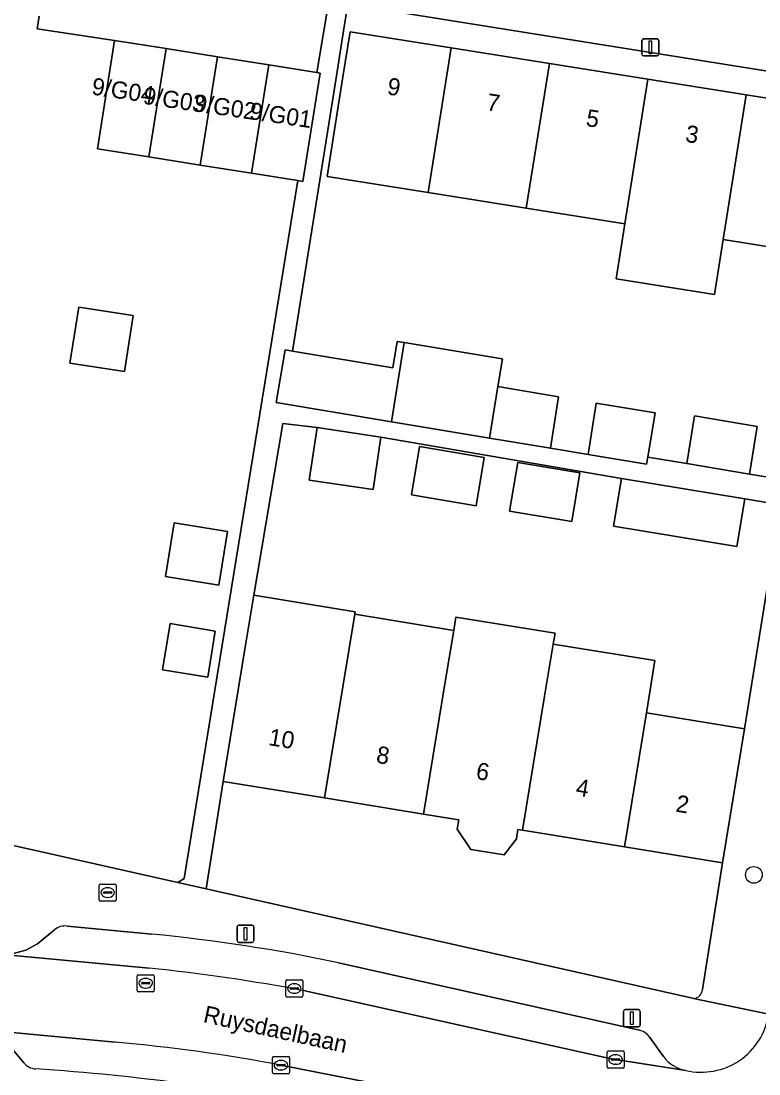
# Model space of a CAD drawing. Extents: x 163008 to 163854, y 382777 to 383982.
# Drawn here: x 163214.9 to 163258.1, y 383050.1 to 383111.7 of the extents above; entities that cross this region are included whole.
import ezdxf

# ---------------------------------------------------------------- set-up
doc = ezdxf.new("R2010")
doc.units = 0
for name, color, linetype in [('IMGEO_Boom', 7, 'Continuous'), ('IMGEO_Brandkraan', 7, 'Continuous'), ('IMGEO_Erf', 7, 'Continuous'), ('IMGEO_Kolk', 7, 'Continuous'), ('IMGEO_Lichtmast', 7, 'Continuous'), ('IMGEO_Muur', 7, 'Continuous'), ('IMGEO_Openbare_ruimte_label', 7, 'Continuous'), ('IMGEO_Pand', 7, 'Continuous'), ('IMGEO_Pand_nummerreeks', 7, 'Continuous'), ('IMGEO_Parkeervlak_open', 7, 'Continuous'), ('IMGEO_Rijbaan_lokaal_open', 7, 'Continuous'), ('IMGEO_Rioolput', 7, 'Continuous'), ('IMGEO_Voetpad_open', 7, 'Continuous')]:
    doc.layers.add(name, color=color, linetype=linetype)

msp = doc.modelspace()

# ---------------------------------------------------------------- linework, layer by layer
at = {"layer": 'IMGEO_Boom'}
msp.add_circle((163257.821, 383061.735), 0.489, dxfattribs=at)
at = {"layer": 'IMGEO_Brandkraan'}
for p, q in [((163219.508, 383060.272), (163219.508, 383061.124)), ((163219.583, 383061.198), (163220.435, 383061.198)), ((163219.996, 383060.978), (163220.021, 383060.978)), ((163220.509, 383061.124), (163220.509, 383060.272)), ((163219.767, 383060.692), (163219.767, 383060.704)), ((163220.205, 383060.655), (163219.807, 383060.655)), ((163219.81, 383060.741), (163220.208, 383060.741)), ((163220.019, 383060.418), (163219.994, 383060.418)), ((163220.251, 383060.704), (163220.251, 383060.692)), ((163220.435, 383060.198), (163219.583, 383060.198))]:
    msp.add_line(p, q, dxfattribs=at)
for points in [[(163219.508, 383060.272), (163219.508, 383061.124)], [(163219.583, 383061.198), (163220.435, 383061.198)], [(163220.509, 383061.124), (163220.509, 383060.272)], [(163220.435, 383060.198), (163219.583, 383060.198)]]:
    msp.add_lwpolyline(points, dxfattribs=at)
for centre, radius, start, end in [((163219.585, 383061.122), 0.0765, 91.55205, 178.44795), ((163219.585, 383061.122), 0.0765, 91.55205, 178.44795), ((163220.433, 383061.122), 0.0765, 1.55205, 88.44795), ((163220.433, 383061.122), 0.0765, 1.55205, 88.44795), ((163219.807, 383060.701), 0.0403, 85.87752, 175.75265), ((163219.804, 383060.691), 0.0366, 178.93798, 274.71019), ((163220.208, 383060.698), 0.043, 264.86636, 352.45326), ((163220.212, 383060.703), 0.0386, 1.73085, 96.63898), ((163219.585, 383060.274), 0.0765, 181.55205, 268.44795), ((163219.585, 383060.274), 0.0765, 181.55205, 268.44795), ((163220.433, 383060.274), 0.0765, 271.55205, 358.44795), ((163220.433, 383060.274), 0.0765, 271.55205, 358.44795)]:
    msp.add_arc(centre, radius, start, end, dxfattribs=at)
for centre, major_axis, ratio, start_param, end_param in [((163219.995, 383060.698), (-0.387, 0.002), 0.722429, 4.712389, 7.853982), ((163220.02, 383060.698), (-0.39, 0.002), 0.717154, 1.570796, 4.712389)]:
    msp.add_ellipse(centre, major_axis=major_axis, ratio=ratio, start_param=start_param, end_param=end_param, dxfattribs=at)
at = {"layer": 'IMGEO_Erf'}
for points in [[(163234.063, 383112.721), (163233.814, 383111.161), (163233.393, 383108.525), (163230.816, 383092.401), (163236.688, 383091.425), (163236.945, 383092.971), (163237.358, 383092.903), (163243.087, 383091.95), (163243.11, 383091.946), (163242.84, 383090.322), (163246.394, 383089.731), (163245.915, 383086.716), (163248.119, 383086.349), (163248.599, 383089.364), (163252.041, 383088.791), (163251.609, 383086.192), (163253.889, 383085.813), (163254.351, 383088.605), (163258.022, 383087.998), (163257.56, 383085.206), (163259.619, 383084.866)], [(163263.52, 383108.014), (163234.432, 383112.662)], [(163220.415, 383110.598), (163215.882, 383111.28), (163216.001, 383112.013)], [(163261.735, 383098.027), (163256.025, 383098.935), (163255.513, 383095.723), (163249.757, 383096.639), (163250.269, 383099.851), (163244.502, 383100.77), (163238.756, 383101.684), (163232.849, 383102.624), (163233.778, 383108.461), (163234.198, 383111.1), (163240.105, 383110.16), (163245.862, 383109.244), (163251.619, 383108.328), (163257.375, 383107.412), (163263.279, 383106.473)], [(163196.948, 383067.404), (163224.107, 383061.294), (163224.491, 383061.52), (163231.133, 383102.385), (163228.425, 383102.816), (163225.418, 383103.294), (163222.412, 383103.772), (163219.405, 383104.251), (163220.415, 383110.598)], [(163241.255, 383063.222), (163240.467, 383064.415), (163240.556, 383064.957), (163238.489, 383065.295), (163232.704, 383066.241), (163226.772, 383067.211), (163225.781, 383060.917), (163254.223, 383054.518), (163254.281, 383054.505)], [(163254.811, 383055.03), (163255.991, 383062.434), (163250.247, 383063.373), (163244.274, 383064.35), (163244.01, 383064.393), (163243.921, 383063.85), (163243.209, 383062.903), (163241.255, 383063.222)]]:
    msp.add_lwpolyline(points, dxfattribs=at)
for points in [[(163217.799, 383091.698), (163218.312, 383094.985), (163221.497, 383094.489), (163220.984, 383091.201)], [(163259.384, 383083.403), (163257.288, 383083.75), (163256.826, 383080.958), (163249.612, 383082.152), (163250.074, 383084.944), (163235.991, 383087.372), (163235.535, 383084.293), (163231.806, 383084.846), (163232.262, 383087.924), (163230.258, 383088.167), (163228.556, 383078.117), (163234.494, 383077.146), (163234.469, 383076.996), (163240.254, 383076.051), (163240.382, 383076.832), (163246.189, 383075.883), (163246.082, 383075.252), (163252.03, 383074.28), (163251.531, 383071.228), (163257.275, 383070.289)], [(163237.783, 383083.98), (163238.254, 383086.811), (163242.048, 383086.18), (163241.578, 383083.349)], [(163243.526, 383083.025), (163244, 383085.871), (163247.632, 383085.267), (163247.159, 383082.421)], [(163223.388, 383079.201), (163223.904, 383082.355), (163227.022, 383081.845), (163226.506, 383078.691)], [(163223.216, 383073.743), (163223.658, 383076.445), (163226.307, 383076.012), (163225.865, 383073.31)]]:
    msp.add_lwpolyline(points, close=True, dxfattribs=at)
msp.add_arc((163254.265, 383055.051), 0.546, 271.66367, 357.79325, dxfattribs=at)
at = {"layer": 'IMGEO_Kolk'}
for p, q in [((163230.431, 383054.656), (163230.431, 383055.508)), ((163230.506, 383055.582), (163231.358, 383055.582)), ((163231.432, 383055.508), (163231.432, 383054.656)), ((163230.69, 383055.076), (163230.69, 383055.088)), ((163231.128, 383055.039), (163230.73, 383055.039)), ((163230.733, 383055.125), (163231.131, 383055.125)), ((163230.919, 383055.362), (163230.944, 383055.362)), ((163231.174, 383055.088), (163231.174, 383055.076)), ((163231.358, 383054.582), (163230.506, 383054.582)), ((163230.942, 383054.802), (163230.917, 383054.802)), ((163249.227, 383050.496), (163249.227, 383051.348)), ((163249.302, 383051.422), (163250.154, 383051.422)), ((163249.715, 383051.202), (163249.74, 383051.202)), ((163250.228, 383051.348), (163250.228, 383050.496)), ((163229.646, 383050.167), (163229.646, 383051.019)), ((163229.721, 383051.093), (163230.573, 383051.093)), ((163229.905, 383050.587), (163229.905, 383050.599)), ((163230.343, 383050.55), (163229.945, 383050.55)), ((163229.948, 383050.636), (163230.346, 383050.636)), ((163230.134, 383050.873), (163230.159, 383050.873)), ((163230.389, 383050.599), (163230.389, 383050.587)), ((163230.647, 383051.019), (163230.647, 383050.167)), ((163249.486, 383050.916), (163249.486, 383050.928)), ((163249.924, 383050.879), (163249.526, 383050.879)), ((163249.529, 383050.965), (163249.927, 383050.965)), ((163249.738, 383050.642), (163249.713, 383050.642)), ((163249.97, 383050.928), (163249.97, 383050.916)), ((163230.573, 383050.093), (163229.721, 383050.093)), ((163230.157, 383050.313), (163230.132, 383050.313)), ((163250.154, 383050.422), (163249.302, 383050.422))]:
    msp.add_line(p, q, dxfattribs=at)
for points in [[(163230.431, 383054.656), (163230.431, 383055.508)], [(163230.506, 383055.582), (163231.358, 383055.582)], [(163231.432, 383055.508), (163231.432, 383054.656)], [(163231.358, 383054.582), (163230.506, 383054.582)], [(163249.227, 383050.496), (163249.227, 383051.348)], [(163249.302, 383051.422), (163250.154, 383051.422)], [(163250.228, 383051.348), (163250.228, 383050.496)], [(163229.646, 383050.167), (163229.646, 383051.019)], [(163229.721, 383051.093), (163230.573, 383051.093)], [(163230.647, 383051.019), (163230.647, 383050.167)], [(163230.573, 383050.093), (163229.721, 383050.093)], [(163250.154, 383050.422), (163249.302, 383050.422)]]:
    msp.add_lwpolyline(points, dxfattribs=at)
for centre, radius, start, end in [((163230.508, 383055.506), 0.0765, 91.55205, 178.44795), ((163230.508, 383055.506), 0.0765, 91.55205, 178.44795), ((163231.356, 383055.506), 0.0765, 1.55205, 88.44795), ((163231.356, 383055.506), 0.0765, 1.55205, 88.44795), ((163230.73, 383055.085), 0.0403, 85.87752, 175.75265), ((163230.727, 383055.075), 0.0366, 178.93798, 274.71019), ((163231.131, 383055.082), 0.043, 264.86636, 352.45326), ((163231.135, 383055.087), 0.0386, 1.73085, 96.63898), ((163230.508, 383054.658), 0.0765, 181.55205, 268.44795), ((163230.508, 383054.658), 0.0765, 181.55205, 268.44795), ((163231.356, 383054.658), 0.0765, 271.55205, 358.44795), ((163231.356, 383054.658), 0.0765, 271.55205, 358.44795), ((163249.304, 383051.346), 0.0765, 91.55205, 178.44795), ((163249.304, 383051.346), 0.0765, 91.55205, 178.44795), ((163250.152, 383051.346), 0.0765, 1.55205, 88.44795), ((163250.152, 383051.346), 0.0765, 1.55205, 88.44795), ((163229.723, 383051.017), 0.0765, 91.55205, 178.44795), ((163229.723, 383051.017), 0.0765, 91.55205, 178.44795), ((163229.945, 383050.596), 0.0403, 85.87752, 175.75265), ((163229.942, 383050.586), 0.0366, 178.93798, 274.71019), ((163230.346, 383050.593), 0.043, 264.86636, 352.45326), ((163230.35, 383050.598), 0.0386, 1.73085, 96.63898), ((163230.571, 383051.017), 0.0765, 1.55205, 88.44795), ((163230.571, 383051.017), 0.0765, 1.55205, 88.44795), ((163249.304, 383050.498), 0.0765, 181.55205, 268.44795), ((163249.304, 383050.498), 0.0765, 181.55205, 268.44795), ((163249.526, 383050.925), 0.0403, 85.87752, 175.75265), ((163249.523, 383050.915), 0.0366, 178.93798, 274.71019), ((163249.927, 383050.922), 0.043, 264.86636, 352.45326), ((163249.931, 383050.927), 0.0386, 1.73085, 96.63898), ((163250.152, 383050.498), 0.0765, 271.55205, 358.44795), ((163250.152, 383050.498), 0.0765, 271.55205, 358.44795), ((163229.723, 383050.169), 0.0765, 181.55205, 268.44795), ((163229.723, 383050.169), 0.0765, 181.55205, 268.44795), ((163230.571, 383050.169), 0.0765, 271.55205, 358.44795), ((163230.571, 383050.169), 0.0765, 271.55205, 358.44795)]:
    msp.add_arc(centre, radius, start, end, dxfattribs=at)
for centre, major_axis, ratio, start_param, end_param in [((163230.918, 383055.082), (-0.387, 0.002), 0.722429, 4.712389, 7.853982), ((163230.943, 383055.082), (-0.39, 0.002), 0.717154, 1.570796, 4.712389), ((163249.714, 383050.922), (-0.387, 0.002), 0.722429, 4.712389, 7.853982), ((163249.739, 383050.922), (-0.39, 0.002), 0.717154, 1.570796, 4.712389), ((163230.133, 383050.593), (-0.387, 0.002), 0.722429, 4.712389, 7.853982), ((163230.158, 383050.593), (-0.39, 0.002), 0.717154, 1.570796, 4.712389)]:
    msp.add_ellipse(centre, major_axis=major_axis, ratio=ratio, start_param=start_param, end_param=end_param, dxfattribs=at)
at = {"layer": 'IMGEO_Lichtmast'}
for p, q in [((163251.268, 383109.787), (163251.268, 383110.587)), ((163251.268, 383110.587), (163251.268, 383109.787)), ((163251.368, 383110.687), (163252.158, 383110.687)), ((163252.158, 383110.687), (163251.368, 383110.687)), ((163252.258, 383110.587), (163252.258, 383109.787)), ((163252.258, 383109.787), (163252.258, 383110.587)), ((163252.158, 383109.687), (163251.368, 383109.687)), ((163251.368, 383109.687), (163252.158, 383109.687)), ((163227.577, 383057.884), (163227.577, 383058.684)), ((163227.577, 383058.684), (163227.577, 383057.884)), ((163227.677, 383058.784), (163228.467, 383058.784)), ((163228.467, 383058.784), (163227.677, 383058.784)), ((163228.567, 383058.684), (163228.567, 383057.884)), ((163228.567, 383057.884), (163228.567, 383058.684)), ((163228.467, 383057.784), (163227.677, 383057.784)), ((163227.677, 383057.784), (163228.467, 383057.784)), ((163250.186, 383052.943), (163250.186, 383053.743)), ((163250.186, 383053.743), (163250.186, 383052.943)), ((163250.286, 383053.843), (163251.076, 383053.843)), ((163251.076, 383053.843), (163250.286, 383053.843)), ((163251.176, 383053.743), (163251.176, 383052.943)), ((163251.176, 383052.943), (163251.176, 383053.743)), ((163251.076, 383052.843), (163250.286, 383052.843)), ((163250.286, 383052.843), (163251.076, 383052.843))]:
    msp.add_line(p, q, dxfattribs=at)
for points in [[(163251.688, 383110.562), (163251.838, 383110.562), (163251.838, 383109.812), (163251.688, 383109.812), (163251.688, 383110.562)], [(163227.997, 383058.659), (163228.147, 383058.659), (163228.147, 383057.909), (163227.997, 383057.909), (163227.997, 383058.659)], [(163250.606, 383053.718), (163250.756, 383053.718), (163250.756, 383052.968), (163250.606, 383052.968), (163250.606, 383053.718)]]:
    msp.add_lwpolyline(points, dxfattribs=at)
for centre, start, end in [((163251.368, 383110.587), 90, 180), ((163251.368, 383110.587), 90, 180), ((163252.158, 383110.587), 0, 90), ((163252.158, 383110.587), 360, 90), ((163251.368, 383109.787), 180, 270), ((163251.368, 383109.787), 180, 270), ((163252.158, 383109.787), 270, 0), ((163252.158, 383109.787), 270, 0), ((163227.677, 383058.684), 90, 180), ((163227.677, 383058.684), 90, 180), ((163228.467, 383058.684), 0, 90), ((163228.467, 383058.684), 360, 90), ((163227.677, 383057.884), 180, 270), ((163227.677, 383057.884), 180, 270), ((163228.467, 383057.884), 270, 0), ((163228.467, 383057.884), 270, 0), ((163250.286, 383053.743), 90, 180), ((163250.286, 383053.743), 90, 180), ((163251.076, 383053.743), 0, 90), ((163251.076, 383053.743), 360, 90), ((163250.286, 383052.943), 180, 270), ((163250.286, 383052.943), 180, 270), ((163251.076, 383052.943), 270, 0), ((163251.076, 383052.943), 270, 0)]:
    msp.add_arc(centre, 0.1, start, end, dxfattribs=at)
at = {"layer": 'IMGEO_Muur'}
msp.add_lwpolyline([(163257.275, 383070.289), (163259.384, 383083.403)], dxfattribs=at)
at = {"layer": 'IMGEO_Pand'}
for points in [[(163240.105, 383110.16), (163234.198, 383111.1), (163233.778, 383108.461), (163232.849, 383102.624), (163238.756, 383101.684)], [(163223.422, 383110.12), (163220.415, 383110.598), (163219.405, 383104.251), (163222.412, 383103.772)], [(163225.418, 383103.294), (163226.429, 383109.641), (163223.422, 383110.12), (163222.412, 383103.772)], [(163240.105, 383110.16), (163238.756, 383101.684), (163244.502, 383100.77), (163245.862, 383109.244)], [(163229.435, 383109.163), (163226.429, 383109.641), (163225.418, 383103.294), (163228.425, 383102.816)], [(163232.442, 383108.684), (163232.25, 383108.715), (163229.435, 383109.163), (163228.425, 383102.816), (163231.133, 383102.385), (163231.432, 383102.337)], [(163251.619, 383108.328), (163245.862, 383109.244), (163244.502, 383100.77), (163250.269, 383099.851)], [(163257.375, 383107.412), (163251.619, 383108.328), (163250.269, 383099.851), (163249.757, 383096.639), (163255.513, 383095.723), (163256.025, 383098.935)], [(163256.025, 383098.935), (163261.735, 383098.027), (163261.93, 383097.996), (163263.279, 383106.473), (163257.375, 383107.412)], [(163217.799, 383091.698), (163220.984, 383091.201), (163221.497, 383094.489), (163218.312, 383094.985)], [(163237.358, 383092.903), (163236.945, 383092.971), (163236.688, 383091.425), (163230.816, 383092.401), (163230.386, 383092.473), (163229.873, 383089.384), (163236.62, 383088.262)], [(163242.342, 383087.31), (163242.84, 383090.322), (163243.11, 383091.946), (163243.087, 383091.95), (163237.358, 383092.903), (163236.62, 383088.262)], [(163246.394, 383089.731), (163242.84, 383090.322), (163242.342, 383087.31), (163245.915, 383086.716)], [(163252.041, 383088.791), (163248.599, 383089.364), (163248.119, 383086.349), (163251.541, 383085.78), (163251.609, 383086.192)], [(163257.56, 383085.206), (163258.022, 383087.998), (163254.351, 383088.605), (163253.889, 383085.813)], [(163232.262, 383087.924), (163231.806, 383084.846), (163235.535, 383084.293), (163235.991, 383087.372)], [(163237.783, 383083.98), (163241.578, 383083.349), (163242.048, 383086.18), (163238.254, 383086.811)], [(163243.526, 383083.025), (163247.159, 383082.421), (163247.632, 383085.267), (163244, 383085.871)], [(163256.826, 383080.958), (163257.288, 383083.75), (163250.074, 383084.944), (163249.612, 383082.152)], [(163223.388, 383079.201), (163226.506, 383078.691), (163227.022, 383081.845), (163223.904, 383082.355)], [(163234.469, 383076.996), (163234.494, 383077.146), (163228.556, 383078.117), (163228.057, 383075.066), (163226.772, 383067.211), (163232.704, 383066.241)], [(163223.216, 383073.743), (163225.865, 383073.31), (163226.307, 383076.012), (163223.658, 383076.445)], [(163239.778, 383073.15), (163240.254, 383076.051), (163234.469, 383076.996), (163232.704, 383066.241), (163238.489, 383065.295)], [(163245.563, 383072.204), (163246.082, 383075.252), (163246.189, 383075.883), (163240.382, 383076.832), (163240.254, 383076.051), (163239.778, 383073.15), (163238.489, 383065.295), (163240.556, 383064.957), (163240.467, 383064.415), (163241.255, 383063.222), (163243.209, 383062.903), (163243.921, 383063.85), (163244.01, 383064.393), (163244.274, 383064.35)], [(163244.274, 383064.35), (163250.247, 383063.373), (163251.531, 383071.228), (163252.03, 383074.28), (163246.082, 383075.252), (163245.563, 383072.204)], [(163250.247, 383063.373), (163255.991, 383062.434), (163257.275, 383070.289), (163251.531, 383071.228)]]:
    msp.add_lwpolyline(points, close=True, dxfattribs=at)
at = {"layer": 'IMGEO_Parkeervlak_open'}
for points in [[(163216.903, 383058.523), (163215.907, 383057.7), (163215.212, 383057.322), (163214.427, 383057.113), (163214.493, 383057.014), (163222.435, 383056.273)], [(163222.584, 383058.266), (163217.637, 383058.738)], [(163251.122, 383052.633), (163233.514, 383056.59)], [(163231.543, 383054.945), (163249.397, 383050.985), (163249.727, 383050.921), (163253.832, 383050.282)], [(163220.449, 383051.941), (163213.372, 383052.604), (163212.774, 383052.68), (163213.503, 383052.384), (163214.13, 383051.894), (163215.105, 383050.732)], [(163252.529, 383051.101), (163251.726, 383052.222)], [(163252.989, 383045.319), (163248.808, 383046.48), (163248.375, 383046.61), (163235.315, 383049.584), (163230.147, 383050.595)]]:
    msp.add_lwpolyline(points, dxfattribs=at)
for centre, radius, start, end in [((163217.524, 383057.764), 0.98, 83.36181, 129.29044), ((163212.795, 382957.949), 100.794, 78.13775, 84.42665), ((163210.919, 382945.392), 111.478, 79.33837, 84.07042), ((163250.974, 383051.766), 0.879, 31.21931, 80.31297), ((163211.356, 382950.817), 101.532, 79.33467, 84.86195), ((163215.869, 383051.349), 0.982, 218.92686, 264.8666), ((163254.222, 383052.349), 2.104, 216.39068, 259.30653), ((163208.147, 382929.517), 121.094, 77.85148, 86.38563)]:
    msp.add_arc(centre, radius, start, end, dxfattribs=at)
at = {"layer": 'IMGEO_Rijbaan_lokaal_open'}
for points in [[(163216.001, 383112.013), (163215.882, 383111.28), (163220.415, 383110.598), (163223.422, 383110.12), (163226.429, 383109.641), (163229.435, 383109.163), (163232.25, 383108.715), (163232.95, 383112.902), (163213.087, 383116.121)], [(163222.435, 383056.273), (163214.493, 383057.014), (163214.427, 383057.113), (163213.659, 383057.003)], [(163253.832, 383050.282), (163249.727, 383050.921), (163249.397, 383050.985), (163231.543, 383054.945)], [(163212.774, 383052.68), (163213.372, 383052.604), (163220.449, 383051.941)], [(163230.147, 383050.595), (163235.315, 383049.584), (163248.375, 383046.61), (163248.808, 383046.48), (163252.989, 383045.319)]]:
    msp.add_lwpolyline(points, dxfattribs=at)
for centre, radius, start, end in [((163210.919, 382945.392), 111.478, 79.33837, 84.07042), ((163254.731, 383054.183), 4.004, 257.02711, 351.27382), ((163211.356, 382950.817), 101.532, 79.33467, 84.86195)]:
    msp.add_arc(centre, radius, start, end, dxfattribs=at)
at = {"layer": 'IMGEO_Rioolput'}
for p, q in [((163221.732, 383054.964), (163221.732, 383055.816)), ((163221.807, 383055.89), (163222.659, 383055.89)), ((163222.034, 383055.433), (163222.432, 383055.433)), ((163222.22, 383055.67), (163222.245, 383055.67)), ((163222.733, 383055.816), (163222.733, 383054.964)), ((163222.659, 383054.89), (163221.807, 383054.89)), ((163221.991, 383055.384), (163221.991, 383055.396)), ((163222.429, 383055.347), (163222.031, 383055.347)), ((163222.243, 383055.11), (163222.218, 383055.11)), ((163222.475, 383055.396), (163222.475, 383055.384))]:
    msp.add_line(p, q, dxfattribs=at)
for points in [[(163221.732, 383054.964), (163221.732, 383055.816)], [(163221.807, 383055.89), (163222.659, 383055.89)], [(163222.733, 383055.816), (163222.733, 383054.964)], [(163222.659, 383054.89), (163221.807, 383054.89)]]:
    msp.add_lwpolyline(points, dxfattribs=at)
for centre, radius, start, end in [((163221.809, 383055.814), 0.0765, 91.55205, 178.44795), ((163221.809, 383055.814), 0.0765, 91.55205, 178.44795), ((163222.031, 383055.393), 0.0403, 85.87752, 175.75265), ((163222.436, 383055.395), 0.0386, 1.73085, 96.63898), ((163222.657, 383055.814), 0.0765, 1.55205, 88.44795), ((163222.657, 383055.814), 0.0765, 1.55205, 88.44795), ((163221.809, 383054.966), 0.0765, 181.55205, 268.44795), ((163221.809, 383054.966), 0.0765, 181.55205, 268.44795), ((163222.028, 383055.383), 0.0366, 178.93798, 274.71019), ((163222.432, 383055.39), 0.043, 264.86636, 352.45326), ((163222.657, 383054.966), 0.0765, 271.55205, 358.44795), ((163222.657, 383054.966), 0.0765, 271.55205, 358.44795)]:
    msp.add_arc(centre, radius, start, end, dxfattribs=at)
for centre, major_axis, ratio, start_param, end_param in [((163222.219, 383055.39), (-0.387, 0.002), 0.722429, 4.712389, 7.853982), ((163222.244, 383055.39), (-0.39, 0.002), 0.717154, 1.570796, 4.712389)]:
    msp.add_ellipse(centre, major_axis=major_axis, ratio=ratio, start_param=start_param, end_param=end_param, dxfattribs=at)
at = {"layer": 'IMGEO_Voetpad_open'}
for points in [[(163271.991, 383163.012), (163270.324, 383152.219), (163270.282, 383151.95), (163270.099, 383150.762), (163268.457, 383140.137), (163267.168, 383132.16), (163266.909, 383130.633), (163266.291, 383126.455), (163266.288, 383126.43), (163264.176, 383112.34), (163264.173, 383112.32), (163263.52, 383108.014), (163263.279, 383106.473), (163261.93, 383097.996), (163261.735, 383098.027), (163259.619, 383084.866), (163259.384, 383083.403), (163257.275, 383070.289), (163255.991, 383062.434), (163254.811, 383055.03)], [(163266.291, 383126.455), (163266.909, 383130.633), (163237.819, 383135.321), (163237.896, 383135.882), (163236.759, 383136.055), (163236.517, 383136.095), (163233.783, 383117.895), (163233.769, 383117.799), (163233.721, 383117.514), (163232.95, 383112.902), (163234.063, 383112.721), (163234.432, 383112.662), (163263.52, 383108.014), (163264.173, 383112.32)], [(163232.95, 383112.902), (163232.25, 383108.715), (163232.442, 383108.684), (163231.432, 383102.337), (163231.133, 383102.385), (163224.491, 383061.52), (163224.107, 383061.294), (163225.781, 383060.917), (163226.772, 383067.211), (163228.057, 383075.066), (163228.556, 383078.117), (163230.258, 383088.167), (163232.262, 383087.924), (163235.991, 383087.372), (163250.074, 383084.944), (163257.288, 383083.75), (163259.384, 383083.403)], [(163259.619, 383084.866), (163257.56, 383085.206), (163253.889, 383085.813), (163251.609, 383086.192), (163251.541, 383085.78), (163248.119, 383086.349), (163245.915, 383086.716), (163242.342, 383087.31), (163236.62, 383088.262), (163229.873, 383089.384), (163230.386, 383092.473), (163230.816, 383092.401), (163233.393, 383108.525), (163233.814, 383111.161), (163234.063, 383112.721)], [(163258.688, 383053.576), (163254.281, 383054.505), (163254.223, 383054.518), (163225.781, 383060.917), (163224.107, 383061.294), (163196.948, 383067.404)], [(163254.281, 383054.505), (163258.688, 383053.576), (163259.673, 383059.48), (163259.821, 383060.729)], [(163213.659, 383057.003), (163214.427, 383057.113), (163215.212, 383057.322), (163215.907, 383057.7), (163216.903, 383058.523)], [(163217.637, 383058.738), (163222.584, 383058.266)], [(163233.514, 383056.59), (163251.122, 383052.633)], [(163215.105, 383050.732), (163214.13, 383051.894), (163213.503, 383052.384), (163212.774, 383052.68)], [(163251.726, 383052.222), (163252.529, 383051.101)]]:
    msp.add_lwpolyline(points, dxfattribs=at)
for centre, radius, start, end in [((163217.524, 383057.764), 0.98, 83.36181, 129.29044), ((163212.795, 382957.949), 100.794, 78.13775, 84.42665), ((163254.265, 383055.051), 0.546, 271.66367, 357.79325), ((163254.731, 383054.183), 4.004, 257.02711, 351.27382), ((163250.974, 383051.766), 0.879, 31.21931, 80.31297), ((163215.869, 383051.349), 0.982, 218.92686, 264.8666), ((163254.222, 383052.349), 2.104, 216.39068, 259.30653), ((163208.147, 382929.517), 121.094, 77.85148, 86.38563)]:
    msp.add_arc(centre, radius, start, end, dxfattribs=at)

# ---------------------------------------------------------------- texts
at = {"layer": 'IMGEO_Openbare_ruimte_label'}
msp.add_text('Ruysdaelbaan', height=1, rotation=347.70114, dxfattribs=at).set_placement((163225.55, 383053.12))
at = {"layer": 'IMGEO_Pand_nummerreeks'}
for s, rotation, p in [('9/G04', 351.57402, (163219.03, 383107.434)), ('9/G03', 351.57402, (163222.035, 383106.89)), ('9', 350.9596, (163236.319, 383107.441)), ('9/G02', 351.57402, (163225.016, 383106.463)), ('7', 350.9596, (163242.136, 383106.516)), ('9/G01', 351.57179, (163228.264, 383105.993)), ('5', 350.95873, (163247.951, 383105.592)), ('3', 350.95873, (163253.767, 383104.666)), ('10', 350.71235, (163229.378, 383069.338)), ('8', 350.71235, (163235.676, 383068.308)), ('6', 350.71235, (163241.515, 383067.354)), ('4', 350.71489, (163247.36, 383066.399)), ('2', 350.71489, (163253.202, 383065.444))]:
    msp.add_text(s, height=1, rotation=rotation, dxfattribs=at).set_placement(p)

doc.saveas('drawing.dxf')
